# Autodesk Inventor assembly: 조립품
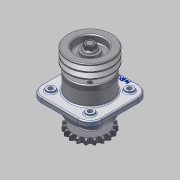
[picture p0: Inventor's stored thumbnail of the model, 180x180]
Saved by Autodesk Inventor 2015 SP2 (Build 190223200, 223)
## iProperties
Created: 2015-07
Part Number: 조립품
Document SubType Name: Assembly
Designer: AMC
Author: AMC
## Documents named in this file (12)
- C:\Users\AMC\Desktop\450735V1009\조립품.iam
- C:\Users\AMC\Desktop\450735V1009\본체.ipt
- C:\Users\AMC\Desktop\450735V1009\2-커버.ipt
- C:\Users\AMC\Desktop\450735V1009\3-축.ipt
- C:\Users\AMC\Desktop\450735V1009\4-V벨트풀리.ipt
- C:\Users\AMC\Desktop\450735V1009\5-체인 스프로킷.ipt
- C:\Users\AMC\Desktop\450735V1009\6-베어링 6206.ipt
- C:\Users\AMC\Desktop\450735V1009\7-부시.ipt
- C:\Users\AMC\Desktop\450735V1009\8-오일실 30x42.ipt
- C:\Users\AMC\Desktop\450735V1009\9-M16-너트.ipt
- C:\Users\AMC\Desktop\450735V1009\10-M6.ipt
- C:\Users\AMC\Desktop\450735V1009\11-키 6x6.ipt
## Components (22 placed, 10 different names)
1. 2-커버:1
2. 3-축:1
3. 4-V벨트풀리:1 — 각도:1
4. 5-체인 스프로킷:1 — 각도:2
5. 6-베어링 6206:1
6. 7-부시:1
7. 8-8-오일실 30x42:1
8. 9-M16 너트:1
9. 11-키 6x6:1 — 각도:1
10. 6-베어링 6206:2
11. 2-커버:2
12. 8-8-오일실 30x42:2
13. 11-키 6x6:2 — 각도:2
14. 9-M16 너트:2
15. 10-M6:2
16. 10-M6:3
17. 10-M6:4
18. 10-M6:5
19. 10-M6:1
20. 10-M6:6
21. 10-M6:7
22. 10-M6:8
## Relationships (2: Angle 2)
- 각도:1 [Angle]: 4-V벨트풀리:1 ↔ 11-키 6x6:1
- 각도:2 [Angle]: 5-체인 스프로킷:1 ↔ 11-키 6x6:2
